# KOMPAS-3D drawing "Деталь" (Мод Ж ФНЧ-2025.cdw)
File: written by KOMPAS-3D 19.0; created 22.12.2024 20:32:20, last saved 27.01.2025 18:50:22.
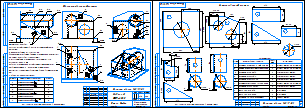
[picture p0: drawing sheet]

Sheets 1-2: A3, landscape

Document properties: Автор: Степан; Полное имя файла: C:\Users\WELDER_72\OneDrive\Desktop\ггавп\КОМПАС 3Д\Мод Ж ФНЧ-2025.cdw; Масса: 6.92787; Форматы листов документа: 2xA3

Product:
- Part/product: Деталь
    Материал: Ст3сп ГОСТ 380-2005 (density 7850 kg/m3)
    Масса: 6.92787
  - Body: Тело 14
      Масса: 0.346028
  - Body: Тело 13
      Масса: 0.318435
  - Body: Тело 10
      Масса: 0.194413
  - Body: Тело 9
      Масса: 0.318795
  - Body: Тело 8
      Масса: 0.346028
  - Body: Тело 7
      Масса: 0.891955
  - Body: Тело 3
      Масса: 0.490532
  - Body: Тело 2
      Масса: 0.791881
  - Body: Тело 1
      Масса: 1.6641
  - Body: Тело 15
      Масса: 1.04195
  - Body: Тело 16
      Масса: 0.159813
  - Body: Тело 17
      Масса: 0.194413
  - Body: Тело 18
      Масса: 0.16953

Title block, sheet 1: Наименование: Модуль Ж / ФНЧ-2025; designation: Процесс сварки 141 (РАД); Материал: Сталь Ст3сп; Масса: 6,93; sheet number: 1; Количество листов документа: 2; organisation: Чемпионат ПМ / "Профессионалы"; Форматы листов документа: A3; stored path: C:\Users\Степан\Desktop\Модули на РЧ\Чертежи\Модуль Ж Степанов.cdw; Разработал: Степанов С.С.; Проверил: Калашников В.А.; Утвердил: Дюкова С. В.
Title block, sheet 2: sheet number: 2

Views: Спереди 1, Спереди, Проекционный вид 2, Проекционный вид 3, Проекционный вид 8
Referenced files in C:\Users\Степан\Desktop\Модули на РЧ\: Модуль Ж на РЧ Степана.m3d
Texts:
  Технические условия:
  1. Сборка производится в любом пространственном
  положении;
  2. Длина прихваток не более 10 мм.
  Располагать прихватки внутри конструкции запрещено;
  3. Наличие зазоров не допускается;
  4. Предоставить конструкцию для контроля без
  собранного узла "7"+"7".
  5. Сварка конструкции производится относительно
  базовой пластины "1", наклонять конструкцию
  запрещено, допускается вращать вокруг вертикальной
  оси;
  6. Сварка на спуск рапрещена;
  № шва
  Стандарт и обозначение
  Кол-во
  ГОСТ 14771-76-Т1- 4 +2
  ГОСТ 14771-76-У4- 4
  ГОСТ 14771-76-С2
  ГОСТ 23518-79-Т5- 4 +2
  ГОСТ 16037-80-С4
  ГОСТ 16037-80-У17- 4 +1
  № дет.
  Наименование, размеры
  шт.
  Пластина 4х250х250 с отв.  110 мм
  Сложная форма, см. чертеж
  Пластина 4х185,25х211 с отв.  70 мм и  75 мм
  Пластина 4х83.5х190
  Прямоугольная форма
  Пластина 4х116х190
  Пластина 4х58х106,75
  Пластина 4х116х65,25 с рад.  44.25 мм
  Пластина 4х106,75х190
  Труба  88,5х4 - 95
  См. чертеж
  Труба  88,5х4 - 125
  Пластина  80,5х4 (заглушка)
  Круглая форма
  Деталировочный чертеж
  Пользовательская 6
  Пользовательская
  Сборочно-сварочный чертеж
  Все расмеры на чертеже указаны в миллиметрах
Dimensions and other numbers on the sheet: 25 2; 2; 1; 7; 8; 9; 4; 3; 5; 6; 250; 125; 110; 140; 211; 185,25; 60; 65,25; 70; 58; 75; 190; 83,5; 116; 106,75; 44,25; 81,05; 21; 88,5; 95; 80,5; 10; 104,25; 26 2; 1:2,5; 6,93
